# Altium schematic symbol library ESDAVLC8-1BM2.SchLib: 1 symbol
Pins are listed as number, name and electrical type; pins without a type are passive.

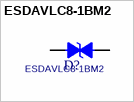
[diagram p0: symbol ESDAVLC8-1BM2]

## ESDAVLC8-1BM2
designator D?
footprint ST_SOD882TB
pins: 1, 2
